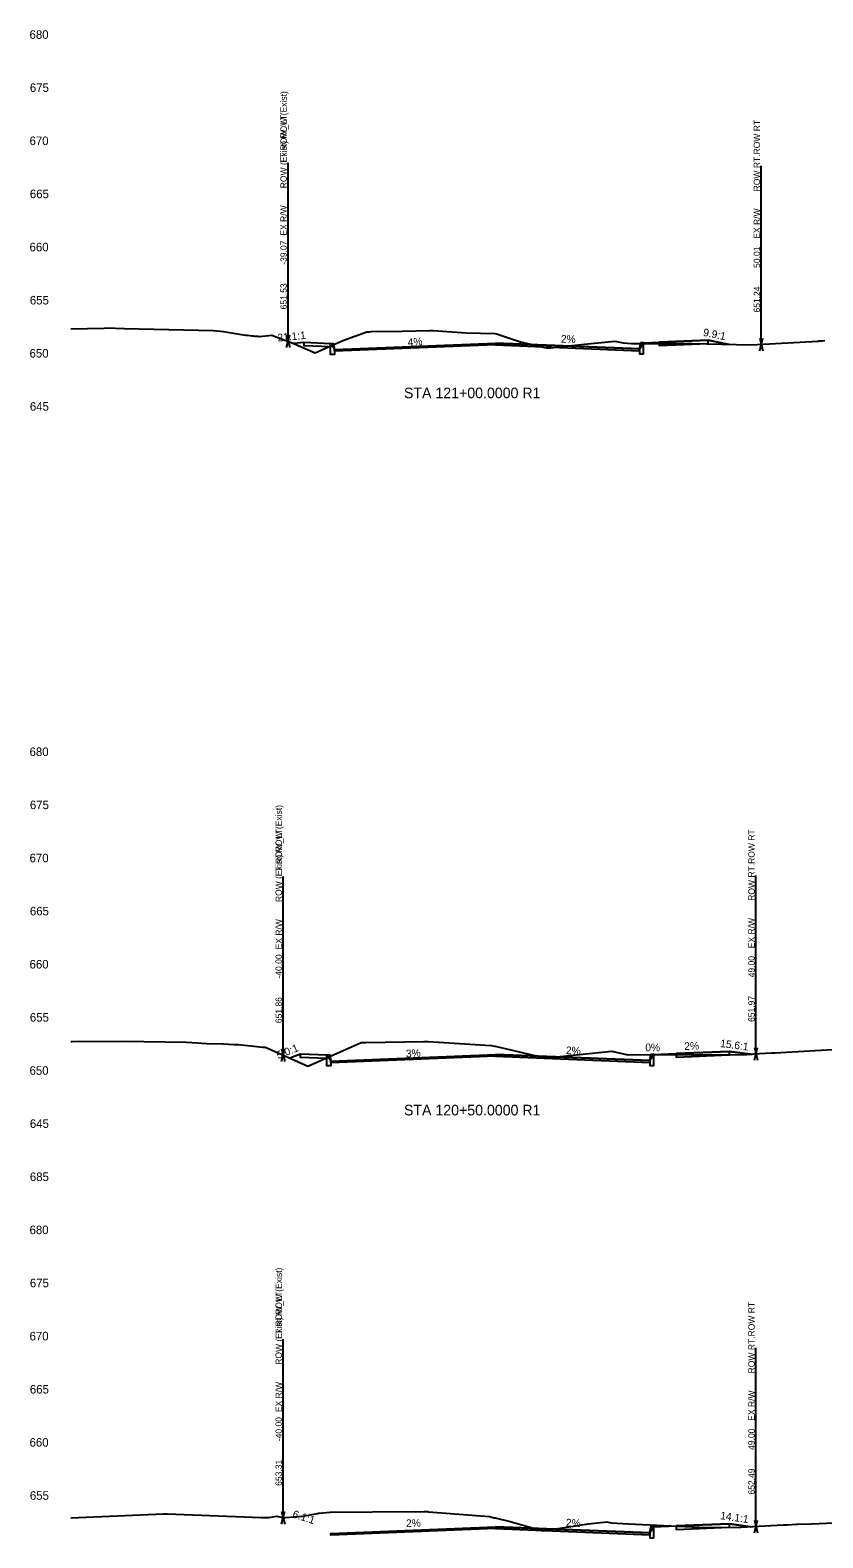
# Model space of a CAD drawing. Extents: x 2 to 741, y 16 to 2207.
# Drawn here: x 2.4 to 151.6, y 267.8 to 551.6 of the extents above; entities that cross this region are included whole.
import ezdxf

# ---------------------------------------------------------------- set-up
doc = ezdxf.new("R2010")
doc.units = 0
for name, color, linetype in [('Draft_XS_Feature_Name', 7, 'Continuous'), ('Draft_XS_Label', 7, 'Continuous'), ('Draft_XS_Point_Label_Indicator', 7, 'Continuous'), ('Draft_XS_Terminator', 7, 'Continuous'), ('Draft_XS_Text', 7, 'Continuous'), ('E_ROW', 7, 'Continuous'), ('E_Terrain_Exterior', 7, 'Continuous'), ('E_Terrain_Points_Low', 7, 'Continuous'), ('Grade_Veg_Grass', 7, 'Continuous'), ('P_XS_Sections', 7, 'Continuous'), ('Road_Curb', 7, 'Continuous'), ('Road_Pave_Asphalt', 7, 'Continuous'), ('Road_Sidewalk', 7, 'Continuous'), ('Terrain_Design', 7, 'Continuous')]:
    doc.layers.add(name, color=color, linetype=linetype)

msp = doc.modelspace()

# ---------------------------------------------------------------- linework, layer by layer
at = {"layer": 'Draft_XS_Terminator'}
for p, q in [((50.93, 493.07), (50.93, 515.07)), ((50.93, 493.07), (50.93, 515.07)), ((140.01, 492.48), (140.01, 514.48)), ((50, 358.71), (50, 380.71)), ((50, 358.71), (50, 380.71)), ((139, 358.94), (139, 380.94)), ((50, 271.62), (50, 293.62)), ((50, 271.62), (50, 293.62)), ((139, 269.99), (139, 291.99))]:
    msp.add_line(p, q, dxfattribs=at)
at = {"layer": 'E_ROW'}
for p, q in [((50.93, 493.07), (50.93, 526.67)), ((50.93, 493.07), (50.93, 526.67)), ((140.01, 492.48), (140.01, 526.08)), ((50.63, 491.87), (51.23, 494.27)), ((50.63, 494.27), (51.23, 491.87)), ((50.63, 491.87), (51.23, 494.27)), ((50.63, 494.27), (51.23, 491.87)), ((139.71, 491.28), (140.31, 493.68)), ((139.71, 493.68), (140.31, 491.28)), ((50, 358.71), (50, 392.31)), ((50, 358.71), (50, 392.31)), ((139, 358.94), (139, 392.54)), ((49.7, 357.51), (50.3, 359.91)), ((49.7, 359.91), (50.3, 357.51)), ((49.7, 357.51), (50.3, 359.91)), ((49.7, 359.91), (50.3, 357.51)), ((138.7, 357.74), (139.3, 360.14)), ((138.7, 360.14), (139.3, 357.74)), ((50, 271.62), (50, 305.22)), ((50, 271.62), (50, 305.22)), ((139, 269.99), (139, 303.59)), ((49.7, 270.42), (50.3, 272.82)), ((49.7, 272.82), (50.3, 270.42)), ((49.7, 270.42), (50.3, 272.82)), ((49.7, 272.82), (50.3, 270.42)), ((138.7, 268.79), (139.3, 271.19)), ((138.7, 271.19), (139.3, 268.79))]:
    msp.add_line(p, q, dxfattribs=at)
at = {"layer": 'E_Terrain_Exterior'}
for points in [[(10, 495.42), (16.32, 495.56), (16.71, 495.57), (20.12, 495.49), (36.85, 495.12), (38.22, 494.98), (38.76, 494.9), (42.91, 494.24), (43.29, 494.2), (43.73, 494.16), (44.09, 494.12), (44.16, 494.11), (44.38, 494.09), (44.63, 494.06), (44.73, 494.05), (44.86, 494.04), (45.07, 494.02), (45.17, 494.01), (45.23, 494), (45.29, 494), (45.38, 493.99), (45.52, 493.97), (45.56, 493.97), (47.86, 494.19), (51.82, 492.74), (56, 490.87), (61.22, 493.19), (65.76, 494.83), (66.2, 494.83), (66.6, 494.88), (72.39, 494.96), (77.6, 495.1), (77.94, 495.11), (78.26, 495.1), (84.46, 494.67), (89.84, 494.51), (90.13, 494.47), (90.75, 494.27), (94.66, 492.96), (99.74, 491.79), (106.1, 492.45), (112.43, 493.12), (114, 492.76), (115.55, 492.66), (126.92, 492.68), (138.07, 492.37), (150.72, 493.12), (150.82, 493.13), (150.93, 493.13), (151.46, 493.16), (151.98, 493.19)], [(10, 361.29), (10.34, 361.29), (19.76, 361.31), (23.78, 361.25), (31.8, 361.13), (33.8, 361), (35.6, 360.88), (38.75, 360.82), (40.71, 360.72), (41.61, 360.68), (45.62, 360.28), (46.15, 360.22), (46.34, 360.2), (46.43, 360.19), (46.48, 360.19), (46.52, 360.18), (46.55, 360.18), (46.57, 360.18), (46.59, 360.18), (46.6, 360.18), (46.61, 360.17), (46.62, 360.17), (46.62, 360.17), (46.62, 360.17), (46.63, 360.17), (46.63, 360.17), (46.64, 360.17), (46.64, 360.17), (46.64, 360.17), (46.64, 360.17), (46.65, 360.17), (46.65, 360.17), (46.65, 360.17), (46.65, 360.17), (46.71, 360.18), (46.8, 360.14), (54.66, 356.63), (64.54, 361.03), (64.71, 361.09), (65.54, 361.09), (65.55, 361.09), (76.5, 361.27), (76.62, 361.27), (77.26, 361.29), (77.27, 361.29), (89.09, 360.48), (89.23, 360.48), (89.77, 360.4), (89.78, 360.39), (89.88, 360.36), (99.54, 358.14), (99.72, 358.16), (111.87, 359.46), (114.9, 358.77), (114.95, 358.77), (137.08, 358.84), (137.24, 358.84), (137.41, 358.85), (137.41, 358.85), (137.41, 358.85), (137.42, 358.85), (137.43, 358.85), (137.44, 358.85), (137.44, 358.85), (137.45, 358.85), (137.45, 358.85), (137.48, 358.85), (137.51, 358.86), (137.52, 358.86), (137.52, 358.86), (137.57, 358.86), (137.65, 358.86), (137.65, 358.86), (137.66, 358.86), (137.78, 358.87), (138.01, 358.88), (138.02, 358.88), (138.02, 358.88), (138.31, 358.9), (138.6, 358.92), (141.87, 359.1), (142.6, 359.15), (143.67, 359.21), (164.18, 360.38)], [(10, 271.6), (27.45, 272.37), (28.15, 272.34), (45.88, 271.66), (47.3, 271.67), (48.84, 271.9), (50.2, 271.57), (50.47, 271.66), (53.73, 271.92), (56.44, 272.41), (56.53, 272.33), (56.67, 272.47), (56.8, 272.48), (58.84, 272.67), (74.74, 272.77), (75.91, 272.76), (76.54, 272.77), (77.2, 272.78), (77.21, 272.78), (77.39, 272.76), (88.86, 271.88), (89.75, 271.59), (89.91, 271.57), (92.76, 270.91), (98.89, 269.14), (107.4, 270.47), (110.9, 270.85), (111.77, 270.65), (115, 270.45), (129.65, 269.8), (136.17, 269.83), (144.14, 270.28), (144.87, 270.31), (146.55, 270.38), (146.69, 270.38), (146.84, 270.39), (149.45, 270.49), (153.73, 270.66)]]:
    msp.add_lwpolyline(points, dxfattribs=at)
at = {"layer": 'Grade_Veg_Grass'}
for points in [[(51.94, 492.69), (53.94, 492.88), (53.94, 492.88)], [(117.86, 492.8), (120.79, 492.92)], [(133.98, 492.48), (129.98, 493.29), (129.98, 493.29)], [(51.25, 358.16), (51.25, 358.16), (53.25, 358.95)], [(119.75, 358.83), (124, 359)], [(138, 358.88), (138, 358.88), (134, 359.4)], [(119.75, 269.93), (124, 270.1)], [(138, 269.93), (138, 269.93), (134, 270.5)]]:
    msp.add_lwpolyline(points, dxfattribs=at)
at = {"layer": 'Road_Curb'}
for points in [[(59.69, 491.51), (59.69, 490.59), (58.94, 490.59), (58.94, 492.68), (59.47, 492.68), (59.69, 491.51)], [(117.11, 491.64), (117.11, 490.72), (117.86, 490.72), (117.86, 492.8), (117.34, 492.8), (117.11, 491.64)], [(59, 357.58), (59, 356.66), (58.25, 356.66), (58.25, 358.75), (58.77, 358.75), (59, 357.58)], [(119, 357.66), (119, 356.74), (119.75, 356.74), (119.75, 358.83), (119.23, 358.83), (119, 357.66)], [(119, 268.76), (119, 267.84), (119.75, 267.84), (119.75, 269.93), (119.23, 269.93), (119, 268.76)]]:
    msp.add_lwpolyline(points, dxfattribs=at)
at = {"layer": 'Road_Pave_Asphalt'}
for points in [[(90, 492.72), (90, 492.39), (59.69, 491.18), (59.69, 491.51), (90, 492.72)], [(90, 492.72), (90, 492.39), (117.11, 491.3), (117.11, 491.64), (90, 492.72)], [(90, 358.82), (90, 358.49), (59, 357.25), (59, 357.58), (90, 358.82)], [(90, 358.82), (90, 358.49), (119, 357.33), (119, 357.66), (90, 358.82)], [(90, 269.92), (90, 269.59), (59, 268.35), (59, 268.68), (90, 269.92)], [(90, 269.92), (90, 269.59), (119, 268.43), (119, 268.76), (90, 269.92)]]:
    msp.add_lwpolyline(points, dxfattribs=at)
at = {"layer": 'Road_Sidewalk'}
for points in [[(58.94, 492.68), (58.94, 492.01), (53.94, 492.21), (53.94, 492.88), (58.94, 492.68)], [(120.79, 492.92), (120.79, 492.25), (129.98, 492.62), (129.98, 493.29), (120.79, 492.92)], [(58.25, 358.75), (58.25, 358.08), (53.25, 358.28), (53.25, 358.95), (58.25, 358.75)], [(124, 359), (124, 358.33), (134, 358.73), (134, 359.4), (124, 359)], [(124, 270.1), (124, 269.43), (134, 269.83), (134, 270.5), (124, 270.1)]]:
    msp.add_lwpolyline(points, dxfattribs=at)
at = {"layer": 'Terrain_Design'}
for points in [[(51.94, 492.69), (53.94, 492.88), (58.94, 492.68), (59.47, 492.68), (59.69, 491.51), (90, 492.72), (117.11, 491.64), (117.34, 492.8), (117.86, 492.8), (120.79, 492.92), (129.98, 493.29), (133.98, 492.48)], [(51.94, 492.69), (53.94, 492.88), (58.94, 492.68), (59.47, 491.87), (59.69, 491.51), (90, 492.72), (117.11, 491.64), (117.34, 491.99), (117.86, 492.8), (120.79, 492.92), (129.98, 493.29), (133.98, 492.48)], [(51.25, 358.16), (51.25, 358.16), (53.25, 358.95), (58.25, 358.75), (58.77, 358.75), (59, 357.58), (90, 358.82), (119, 357.66), (119.23, 358.83), (119.75, 358.83), (124, 359), (134, 359.4), (138, 358.88)], [(51.25, 358.16), (51.25, 358.16), (53.25, 358.95), (58.25, 358.75), (58.77, 357.94), (59, 357.58), (90, 358.82), (119, 357.66), (119.23, 358.02), (119.75, 358.83), (124, 359), (134, 359.4), (138, 358.88)], [(59, 268.68), (90, 269.92), (119, 268.76), (119.23, 269.93), (119.75, 269.93), (124, 270.1), (134, 270.5), (138, 269.93)], [(59, 268.68), (90, 269.92), (119, 268.76), (119.23, 269.12), (119.75, 269.93), (124, 270.1), (134, 270.5), (138, 269.93)]]:
    msp.add_lwpolyline(points, dxfattribs=at)

# ---------------------------------------------------------------- texts
at = {"layer": 'Draft_XS_Feature_Name'}
for s, p in [('ROW (Exist).ROW (Exist)', (50.69, 521.87)), ('ROW_LT.ROW_LT', (50.69, 521.87)), ('ROW RT.ROW RT', (139.77, 521.28)), ('ROW (Exist).ROW (Exist)', (49.76, 387.51)), ('ROW_LT.ROW_LT', (49.76, 387.51)), ('ROW RT.ROW RT', (138.76, 387.74)), ('ROW (Exist).ROW (Exist)', (49.76, 300.42)), ('ROW_LT.ROW_LT', (49.76, 300.42)), ('ROW RT.ROW RT', (138.76, 298.79))]:
    msp.add_text(s, height=1.2, rotation=90, dxfattribs=at).set_placement(p)
at = {"layer": 'Draft_XS_Label'}
for s, p in [('-39.07', (50.69, 507.47)), ('-39.07', (50.69, 507.47)), ('50.01', (139.77, 506.88)), ('651.53', (50.69, 499.07)), ('651.53', (50.69, 499.07)), ('651.24', (139.77, 498.48)), ('-40.00', (49.76, 373.11)), ('-40.00', (49.76, 373.11)), ('49.00', (138.76, 373.34)), ('651.86', (49.76, 364.71)), ('651.86', (49.76, 364.71)), ('651.97', (138.76, 364.94)), ('-40.00', (49.76, 286.02)), ('-40.00', (49.76, 286.02)), ('49.00', (138.76, 284.39)), ('653.31', (49.76, 277.62)), ('653.31', (49.76, 277.62)), ('652.49', (138.76, 275.99))]:
    msp.add_text(s, height=1.2, rotation=90, dxfattribs=at).set_placement(p)
at = {"layer": 'Draft_XS_Point_Label_Indicator'}
for p in [(51.93, 492.67), (53.93, 492.86), (58.93, 492.66), (59.45, 492.66), (59.68, 491.5), (117.1, 491.62), (117.33, 492.79), (117.85, 492.79), (120.77, 492.91), (129.97, 493.28), (133.97, 492.47), (59.68, 490.58), (117.1, 490.71), (51.24, 358.14), (53.24, 358.94), (58.24, 358.74), (58.76, 358.74), (58.99, 357.57), (118.99, 357.65), (119.22, 358.82), (119.74, 358.82), (123.99, 358.99), (133.99, 359.39), (137.99, 358.87), (58.99, 356.65), (118.99, 356.73), (119.22, 269.92), (119.74, 269.92), (123.99, 270.09), (133.99, 270.49), (137.99, 269.92), (58.99, 268.67), (118.99, 268.75), (118.99, 267.83)]:
    msp.add_text('X', height=0.024, dxfattribs=at).set_placement(p)
at = {"layer": 'Draft_XS_Text'}
for s, height, p in [('680', 1.608, (2.26, 550)), ('675', 1.608, (2.32, 540)), ('670', 1.608, (2.26, 530)), ('665', 1.608, (2.32, 520)), ('660', 1.608, (2.26, 510)), ('655', 1.608, (2.32, 500)), ('650', 1.608, (2.26, 490)), ('STA 121+00.0000 R1', 1.992, (72.74, 482.35)), ('645', 1.608, (2.32, 480)), ('680', 1.608, (2.26, 415)), ('675', 1.608, (2.32, 405)), ('670', 1.608, (2.26, 395)), ('665', 1.608, (2.32, 385)), ('660', 1.608, (2.26, 375)), ('655', 1.608, (2.32, 365)), ('0%', 1.44, (118.17, 359.43)), ('650', 1.608, (2.26, 355)), ('STA 120+50.0000 R1', 1.992, (72.74, 347.35)), ('645', 1.608, (2.32, 345)), ('685', 1.608, (2.32, 335)), ('680', 1.608, (2.26, 325)), ('675', 1.608, (2.32, 315)), ('670', 1.608, (2.26, 305)), ('665', 1.608, (2.32, 295)), ('660', 1.608, (2.26, 285)), ('655', 1.608, (2.32, 275))]:
    msp.add_text(s, height=height, dxfattribs=at).set_placement(p)
for s, rotation, p in [('21.1:1', 5.4082, (48.99, 493.01)), ('2%', 357.7094, (102.26, 492.83)), ('9.9:1', 348.6324, (128.97, 494.1)), ('4%', 4.0183, (73.49, 492.16)), ('5.0:1', 21.612, (49.05, 357.93)), ('2%', 2.2906, (125.54, 359.66)), ('15.6:1', 352.6803, (132.2, 360.23)), ('3%', 3.9796, (73.15, 358.25)), ('2%', 357.7094, (103.21, 358.89)), ('6.1:1', 341.9257, (51.64, 271.71)), ('14.1:1', 351.9501, (132.21, 271.36)), ('2%', 2.2906, (73.16, 269.85)), ('2%', 357.7094, (103.21, 269.99))]:
    msp.add_text(s, height=1.44, rotation=rotation, dxfattribs=at).set_placement(p)
at = {"layer": 'E_ROW'}
for p in [(50.69, 512.95), (50.69, 512.95), (139.77, 512.37), (49.76, 378.6), (49.76, 378.6), (138.76, 378.82), (49.76, 291.5), (49.76, 291.5), (138.76, 289.87)]:
    msp.add_text('EX R/W', height=1.2, rotation=90, dxfattribs=at).set_placement(p)
at = {"layer": 'E_Terrain_Points_Low'}
for p in [(89.99, 492.71), (89.99, 358.81), (89.99, 269.91)]:
    msp.add_text('X', height=0.024, dxfattribs=at).set_placement(p)
at = {"layer": 'P_XS_Sections'}
for p in [(10, 480), (10, 345)]:
    msp.add_text('-', height=0.0001, dxfattribs=at).set_placement(p)

doc.saveas('drawing.dxf')
